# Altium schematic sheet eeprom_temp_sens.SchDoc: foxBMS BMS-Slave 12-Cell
size A3; DocumentNumber: 9; SheetNumber: 9; SheetTotal: 15; AUTHOR: Fraunhofer IISB foxBMS Team; SheetDescription: Primary EEPROM and Board T-Sensor
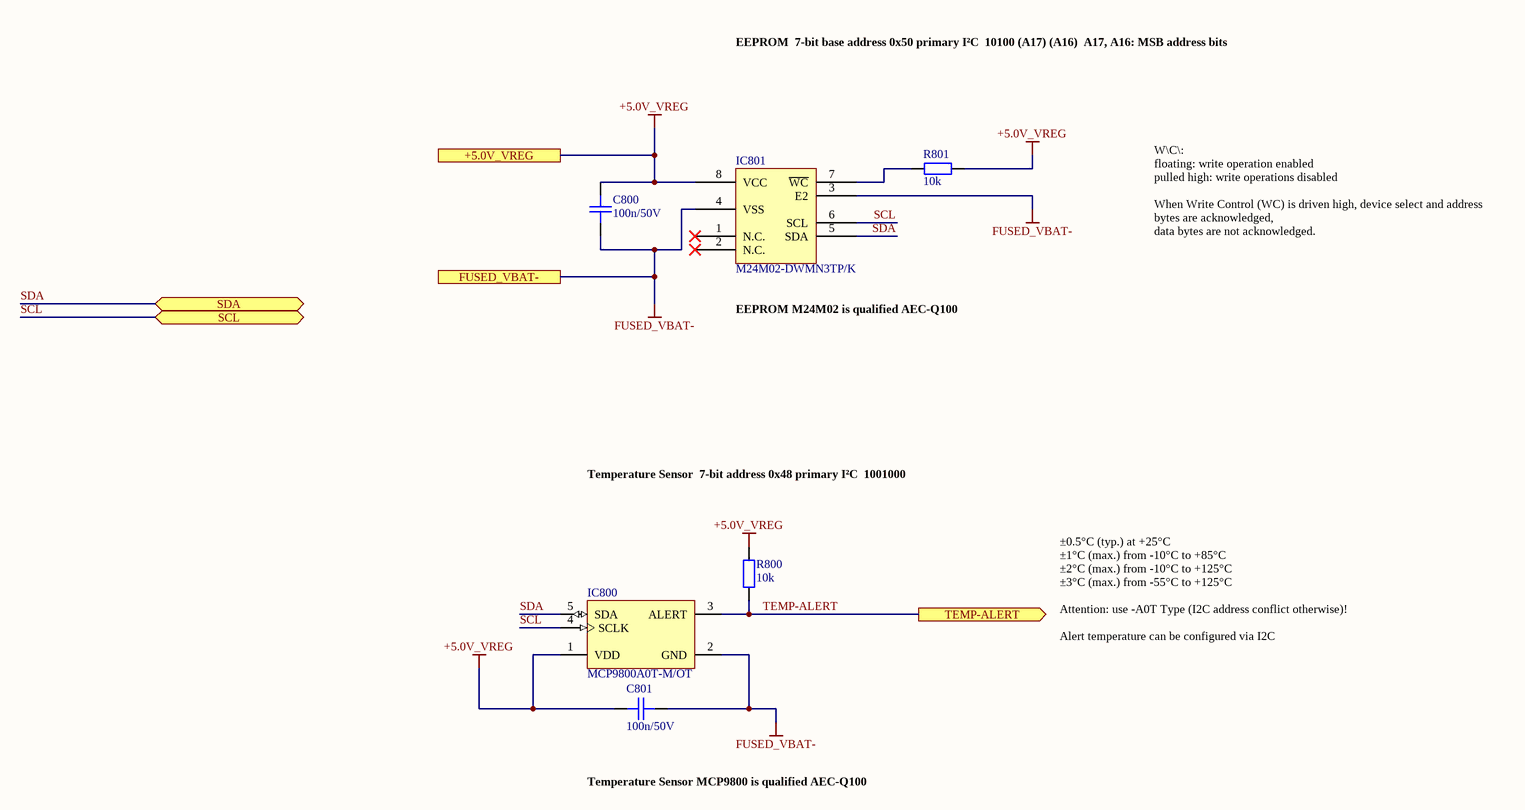
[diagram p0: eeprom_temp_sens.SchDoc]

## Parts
C800  100n/50V  [CAPC1608X08N]
C801  100n/50V  [CAPC1608X08N]
IC800  MCP9800A0T-M/OT  [SOT-23-OT5_L]
IC801  M24M02-DWMN3TP/K  [SOIC127P600X175-8N]
R800  10k  [RESC1608X05N]
R801  10k  [RESC1608X05N]

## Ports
+5.0V_VREG, FUSED_VBAT-, SCL (bidir), SDA (bidir), TEMP-ALERT (out)

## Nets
+5.0V_VREG: C800.2 C801.2 IC800.1(VDD) IC801.8(VCC) R800.2 R801.2 ; port +5.0V_VREG
FUSED_VBAT-: C800.1 C801.1 IC800.2(GND) IC801.3(E2) IC801.4(VSS) ; port FUSED_VBAT-
SCL: IC800.4(SCLK) IC801.6(SCL) ; port SCL
SDA: IC800.5(SDA) IC801.5(SDA) ; port SDA
TEMP-ALERT: IC800.3(ALERT) R800.1 ; port TEMP-ALERT
NetIC801_7: IC801.7(~{WC}) R801.1

Not connected (* = marked no-connect by the designer): IC801 1(N.C.)* 2(N.C.)*

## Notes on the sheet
- EEPROM
  7-bit base address 0x50 primary I²C
  10100 (A17) (A16)
  A17, A16: MSB address bits
- W\C\:
  floating: write operation enabled
  pulled high: write operations disabled
  When Write Control (WC) is driven high, device select and address bytes are acknowledged,
  data bytes are not acknowledged.
- EEPROM M24M02 is qualified AEC-Q100
- Temperature Sensor
  7-bit address 0x48 primary I²C
  1001000
- ±0.5°C (typ.) at +25°C
  ±1°C (max.) from -10°C to +85°C
  ±2°C (max.) from -10°C to +125°C
  ±3°C (max.) from -55°C to +125°C
  Attention: use -A0T Type (I2C address conflict otherwise)!
  Alert temperature can be configured via I2C
- Temperature Sensor MCP9800 is qualified AEC-Q100

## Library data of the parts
C800 C801 = gen_C_ceramic_100n_50V_X7R_0603: MLCC; Capacitance: 100n; Rated Voltage: 50V; Dielectric: X7R; Case EIA: 0603; Case Metric: 1608; PnP Package: C_0603_10; PnP Value: 100n/50V/X7R; PnP equipped: x; Automotive Qualified: True
IC800 = CMP-0192-00211-1: 2-Wire High-Accuracy Temperature Sensor, Slave Address 000, 5-Pin SOT-23, -55°C to +125°C Temperature, Tape and Reel
IC801 = M24M02-DWMN3TP/K: Automotive 2-Mbit serial I²C / bus EEPROM with 1 MHz clock; Manufacturer: STMicroelectronics; PnP Package: SO8N; Automotive Qualified: True
R800 R801 = gen_R_10k_0603: SMD Resistor 10k 0603; Tolerance: 1%; Power: 0.1W; Case EIA: 0603; Case Metric: 1608; Maximum Working Voltage: 75V; PnP Package: R_0603; Automotive Qualified: True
